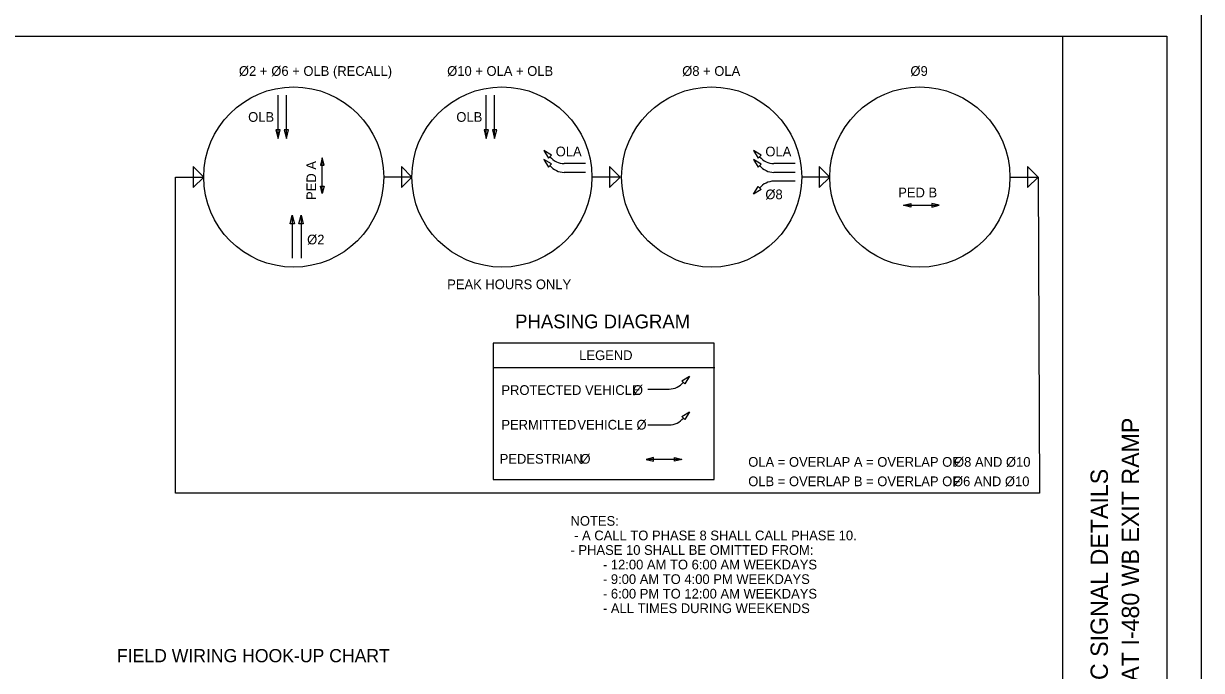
# Model space of a CAD drawing. Extents: x 680 to 2132, y 0 to 656.
# Drawn here: x 1020 to 1360, y 247 to 433.6 of the extents above; entities that cross this region are included whole.
import ezdxf

# ---------------------------------------------------------------- set-up
doc = ezdxf.new("R2010")
doc.units = 0
for name, color, linetype in [('SH_Border', 7, 'Continuous'), ('SH_Cut_Line', 7, 'Continuous'), ('SH_Data', 7, 'Continuous'), ('SH_Text', 7, 'Continuous')]:
    doc.layers.add(name, color=color, linetype=linetype)

msp = doc.modelspace()

# ---------------------------------------------------------------- linework, layer by layer
at = {"layer": 'SH_Border'}
msp.add_line((1320, 10), (1320, 430), dxfattribs=at)
msp.add_lwpolyline([(710, 430), (1350, 430), (1350, 10), (710, 10)], close=True, dxfattribs=at)
at = {"layer": 'SH_Cut_Line'}
msp.add_lwpolyline([(680, 0), (1360, 0), (1360, 440), (680, 440)], close=True, dxfattribs=at)
at = {"layer": 'SH_Data'}
for p, q in [((1093.46, 400.47), (1093.46, 412.93)), ((1095.87, 400.47), (1095.87, 412.93)), ((1153.57, 400.47), (1153.57, 412.93)), ((1155.97, 400.47), (1155.97, 412.93)), ((1106.24, 384.59), (1106.24, 394.86)), ((1182.2, 393.22), (1176.08, 393.22)), ((1242.72, 393.22), (1236.61, 393.22)), ((1132.1, 389.34), (1123.98, 389.34)), ((1182.2, 390.68), (1176.08, 390.68)), ((1192.21, 389.34), (1184.08, 389.34)), ((1242.72, 390.68), (1236.61, 390.68)), ((1242.72, 388.14), (1236.61, 388.14)), ((1252.73, 389.34), (1244.61, 389.34)), ((1274.01, 381.19), (1284.27, 381.19)), ((1097.56, 378.38), (1097.56, 365.93)), ((1100.1, 378.38), (1100.1, 365.93)), ((1155.5, 334.44), (1219.54, 334.44)), ((1200.22, 328.18), (1206.33, 328.18)), ((1200.22, 317.84), (1206.33, 317.84)), ((1210, 307.88), (1199.73, 307.88))]:
    msp.add_line(p, q, dxfattribs=at)
for points in [[(1092.84, 402.97), (1093.46, 400.47), (1094.09, 402.97)], [(1095.24, 402.97), (1095.87, 400.47), (1096.49, 402.97)], [(1152.94, 402.97), (1153.57, 400.47), (1154.19, 402.97)], [(1155.35, 402.97), (1155.97, 400.47), (1156.6, 402.97)], [(1106.76, 392.77), (1106.24, 394.86), (1105.72, 392.77)], [(1172.4, 395.65), (1170.18, 396.97), (1171.51, 394.76)], [(1172.4, 393.11), (1170.18, 394.43), (1171.51, 392.22)], [(1232.92, 395.64), (1230.71, 396.97), (1232.04, 394.76)], [(1232.92, 393.1), (1230.71, 394.43), (1232.04, 392.22)], [(1071.99, 389.34), (1068.96, 392.37), (1068.96, 386.31)], [(1132.1, 389.34), (1129.07, 392.37), (1129.07, 386.31)], [(1192.21, 389.34), (1189.18, 392.37), (1189.17, 386.31)], [(1252.73, 389.34), (1249.7, 392.37), (1249.7, 386.31)], [(1312.84, 389.34), (1309.81, 392.37), (1309.8, 386.31)], [(1106.76, 386.67), (1106.24, 384.59), (1105.72, 386.67)], [(1232.92, 385.72), (1230.71, 384.39), (1232.04, 386.6)], [(1276.09, 380.67), (1274.01, 381.19), (1276.09, 381.71)], [(1282.19, 380.67), (1284.27, 381.19), (1282.19, 381.71)], [(1096.93, 375.88), (1097.56, 378.38), (1098.19, 375.88)], [(1099.47, 375.88), (1100.1, 378.38), (1100.72, 375.88)], [(1219.32, 341.44), (1155.55, 341.44), (1155.55, 302.12), (1219.32, 302.12)], [(1210.02, 330.6), (1212.23, 331.92), (1210.91, 329.72)], [(1210.02, 320.26), (1212.24, 321.58), (1210.91, 319.38)], [(1201.82, 308.4), (1199.73, 307.88), (1201.82, 307.36)], [(1207.91, 308.4), (1210, 307.88), (1207.91, 307.36)]]:
    msp.add_lwpolyline(points, close=True, dxfattribs=at)
msp.add_lwpolyline([(1304.72, 389.34), (1312.84, 389.34), (1313.24, 298.12), (1063.87, 298.11), (1063.87, 389.34), (1071.99, 389.34)], dxfattribs=at)
for centre in [(1097.98, 389.34), (1158.09, 389.34), (1218.62, 389.34), (1278.72, 389.34)]:
    msp.add_circle(centre, 25.99, dxfattribs=at)
for centre, start, end in [((1176.09, 398.52), 218.7864, 269.9871), ((1236.61, 398.52), 218.7864, 269.9871), ((1176.09, 395.98), 218.7864, 269.9871), ((1236.61, 395.98), 218.7864, 269.9871), ((1236.61, 382.84), 90.0129, 141.2136), ((1206.33, 333.48), 270.0129, 321.2136), ((1206.33, 323.14), 270, 321.2007)]:
    msp.add_arc(centre, 5.3, start, end, dxfattribs=at)

# ---------------------------------------------------------------- texts
for s, p in [('CLAGUE RD AT I-480 WB EXIT RAMP', (1342, 202.91)), ('TRAFFIC SIGNAL DETAILS', (1333, 220.85))]:
    msp.add_text(s, height=5, rotation=90, dxfattribs=at).set_placement(p)
at = {"layer": 'SH_Text'}
for s, height, p in [('Ø', 2.8, (1082.16, 418.53)), ('2 + ', 2.8, (1085.08, 418.53)), ('Ø', 2.8, (1091.51, 418.53)), ('6 + OLB (RECALL)', 2.8, (1094.43, 418.53)), ('Ø10 + OLA + OLB', 2.8, (1142.28, 418.53)), ('Ø', 2.8, (1210.12, 418.53)), ('8 + OLA', 2.8, (1213.04, 418.53)), ('Ø', 2.8, (1276, 418.53)), ('9', 2.8, (1278.92, 418.53)), ('OLB', 2.8, (1084.83, 405.27)), ('OLB', 2.8, (1144.93, 405.27)), ('OLA', 2.8, (1173.61, 395.32)), ('OLA', 2.8, (1234.13, 395.31)), ('Ø8', 2.8, (1234.13, 382.94)), ('PED B', 2.8, (1272.48, 383.48)), ('Ø', 2.8, (1101.85, 369.92)), ('2', 2.8, (1104.77, 369.92)), ('PEAK HOURS ONLY', 2.8, (1142.28, 357)), ('PHASING DIAGRAM', 4, (1161.89, 345.69)), ('LEGEND', 2.8, (1180.39, 336.54)), ('PROTECTED VEHICLE ', 2.8, (1157.93, 326.5)), ('Ø', 2.8, (1195.88, 326.5)), ('PERMITTED ', 2.8, (1157.93, 316.5)), ('VEHICLE Ø', 2.8, (1179.87, 316.5)), ('PEDESTRIAN ', 2.8, (1157.44, 306.66)), ('Ø', 2.8, (1180.75, 306.66)), ('OLA = OVERLAP A = OVERLAP OF ', 2.8, (1229.18, 305.77)), ('Ø8 AND Ø10', 2.8, (1288.59, 305.77)), ('OLB = OVERLAP B = OVERLAP OF ', 2.8, (1229.18, 300.17)), ('Ø6 AND Ø10', 2.8, (1288.29, 300.17)), ('NOTES:', 2.8, (1177.88, 288.76)), (' - A CALL TO PHASE 8 SHALL CALL PHASE 10.', 2.8, (1177.88, 284.56)), ('- PHASE 10 SHALL BE OMITTED FROM:', 2.8, (1177.88, 280.36)), ('         - 12:00 AM TO 6:00 AM WEEKDAYS', 2.8, (1177.88, 276.16)), ('         - 9:00 AM TO 4:00 PM WEEKDAYS', 2.8, (1177.88, 271.96)), ('         - 6:00 PM TO 12:00 AM WEEKDAYS', 2.8, (1177.88, 267.76)), ('         - ALL TIMES DURING WEEKENDS', 2.8, (1177.88, 263.56)), ('FIELD WIRING HOOK-UP CHART', 3.8, (1046.96, 249.39))]:
    msp.add_text(s, height=height, dxfattribs=at).set_placement(p)
msp.add_text('PED A', height=2.8, rotation=90, dxfattribs=at).set_placement((1104.46, 382.73))

doc.saveas('drawing.dxf')
